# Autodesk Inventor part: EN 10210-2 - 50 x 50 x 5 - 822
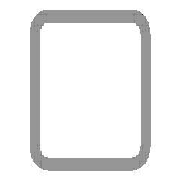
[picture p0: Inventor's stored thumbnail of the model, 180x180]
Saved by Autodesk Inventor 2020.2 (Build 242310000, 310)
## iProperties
IsCustomPart: 1
_CCFamilyMember: 16
_CCFamilyDisplayName: DIN EN 10210-2 (USAS B17.1 quadratisch) - Rohrleitung — In Klammern angegebene Größen wurden aufgehoben
_FrameMemberDoc: Frame Member File
_Version: 15.0.0
_GetPNFromCC: 1
Created: 2019-10
Part Number: EN 10210-2 - 50 x 50 x 5 - 822
Material: Stahl, weich
Description: Rohrleitung
Document SubType Name: Modeling
Standard: DIN
Designer: lutzd
Standard Revision: 2006-07
Standards Organization: DIN
Language: de-DE
Size Designation: 50 x 50 x 5
Categories: <MemberInstance><Categories><Category DisplayName="Profile" InternalName="089c4875-fa83-4c05-b084-43b9cc11f5ed" Mnemonic="GRDR"><CategoryParameter DisplayName="
Stock Number: 50 x 50 x 5
Mass: 5628.89 g
Surface Area: 2801.66 cm^2
Volume: 717.056 cm^3
Density: 7.85 g/cm^3
Appearance: Semi-Polished(8)
G_L: 822,000 mm
G_W: 50,000 mm
G_H: 50,000 mm
Dimensions: 50x50x822 mm
Mass: 5,629 kg
DocNumber: ADSK-014284
Folder: .
+0557A8AD-6592-445A-8F45-BF1A513C252D+SCHNITTDETAIL1: Schnittwinkel 90,00 grd
+76BFF194-B2E9-489A-8870-1F0FEFEF03AC+SCHNITTDETAIL2: Schnittwinkel 90,00 grd
VLT_Material: Stahl, weich
Title: Profil-Bauteil
Author: lutzd
Revision Number: -
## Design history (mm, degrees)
node "Startebene"
node "Endebene"
sketch "Skizze"
  geometry: L1 (-25, -17.5)-(-25, 17.5); L2 (-17.5, 25)-(17.5, 25); L3 (25, 17.5)-(25, -17.5); L4 (17.5, -25)-(-17.5, -25); L5 (-15, 20)-(15, 20); L6 (20, 15)-(20, -15); L7 (15, -20)-(-15, -20); L8 (-20, -15)-(-20, 15); L9 (0, 37.175)-(0, -37.175) reference; L10 (-37.175, 0)-(37.175, 0) reference; A1 r 7.5 centre (-17.5, -17.5) between (-25, -17.5) and (-17.5, -25); A2 r 7.5 centre (-17.5, 17.5) between (-17.5, 25) and (-25, 17.5); A3 r 7.5 centre (17.5, 17.5) between (25, 17.5) and (17.5, 25); A4 r 7.5 centre (17.5, -17.5) between (17.5, -25) and (25, -17.5); A5 r 5 centre (-15, -15) between (-20, -15) and (-15, -20); A6 r 5 centre (-15, 15) between (-15, 20) and (-20, 15); A7 r 5 centre (15, 15) between (20, 15) and (15, 20); A8 r 5 centre (15, -15) between (15, -20) and (20, -15)
  constraints: 16 end point, 16 point on circle, 16 tangent, 8 centre point, 6 equal radius, 4 parallel, 2 perpendicular, 2 other
  dimensions: "d7" = 7.5 radius of A1 (= G_IR); "d10" = 50 distance between parallel lines of L2 L4 (= G_H); "d11" = 50 distance between parallel lines of L1 L3 (= G_W); "d12" = 5 distance between parallel lines of L3 L6 (= G_T); "d15" = 25 distance between parallel lines of L2 L10 (= 0.5 x d10); "d16" = 25 distance between parallel lines of L9 L3 (= 0.5 x d11); "d19" = 5 radius of A5 (= G_T); "d20" = 5 distance between parallel lines of L4 L7 (= G_T)
extrude "Körper" new body sketch "Skizze" stored distance "d3" = 822 (= G_L); taper "d4" = 0 deg
node "Driven Length"
  sketch "Sketch3"
    geometry: L1 (0, 0)-(10, 0) reference
    constraints: 2 end point, 1 horizontal
  workplane "Work Plane3"
  sketch "Sketch4"
    geometry: L1 (-2, 50)-(12, 50) reference; L2 (-2, 872)-(12, 872) reference
    dimensions: "d18" = 822 distance between parallel lines of L1 L2 (derived)
workplane "Arbeitsebene4"
feature "Trennen1"
workplane "Arbeitsebene5"
feature "Trennen2"
sketch "Skizze5"
  geometry: L1 (822, 35)-(822, 0) reference; L2 (822, 17.5)-(513.475, 17.5); L3 (429, 17.5)-(389, 17.5); 6 further points
  constraints: 4 end point, 3 coincident, 2 horizontal, 2 midpoint, 1 collinear, 1 point on line
  dimensions: "d22" = 203 distance of point (513.475, 17.5) point (716.475, 17.5); "d23" = 105.525 distance from line of point (716.475, 17.5) L1; "d31" = 40 distance of L3.start L3.end; "d32" = 413 distance from line of L1 point (409, 17.5)
hole "Bohrung1" sketch "Skizze5" at (513.475, 17.5), (716.475, 17.5), (389, 17.5), (429, 17.5) diameter "d24" = 6.647; stored, may be unused: countersink angle "d28" = 90 deg, drill point angle "d30" = 118 deg; dims "d25" = 16, "d26" = 4, "d27" = 2, "d29" = 8
body "Solid1"
other parameters: "G_W" = 50 [user parameter; used in 1 equation term], "G_H" = 50 [user parameter; used in 1 equation term], "G_T" = 5 [user parameter; used in 3 equation terms], "G_IR" = 7.5 [user parameter; used in 1 equation term], "G_L" = 822 (= d18) [user parameter; used in 1 equation term], "G_OFFSET_END" = -25 [user parameter; used in 1 equation term], "d14" = 872 (= G_OFFSET_END + B_L), "B_L" = 897 [user parameter; used in 1 equation term], "d17" = 90 deg
